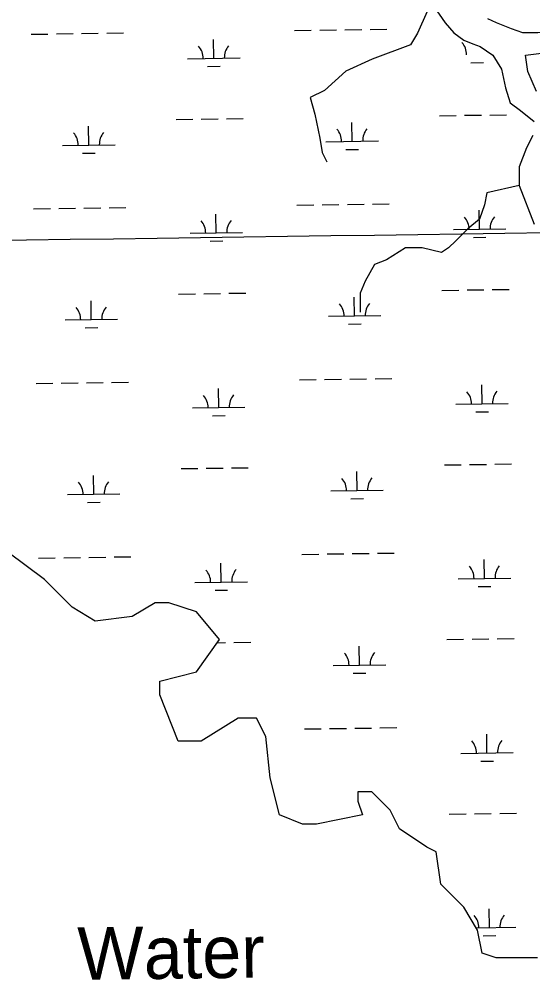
# Model space of a CAD drawing. Extents: x 3775218 to 3813389, y 343470 to 369318.
# Drawn here: x 3788802 to 3789781, y 353674 to 355504 of the extents above; entities that cross this region are included whole.
import ezdxf

# ---------------------------------------------------------------- set-up
doc = ezdxf.new("R2010")
doc.units = 0
for name, color, linetype in [('V-GRID-MAJR', 7, 'Continuous'), ('V-RIVR-IDEN', 7, 'Continuous'), ('V-TOPO-SHOR', 7, 'Continuous'), ('V-WETL-SWMP', 7, 'Continuous')]:
    doc.layers.add(name, color=color, linetype=linetype)

msp = doc.modelspace()

# ---------------------------------------------------------------- linework, layer by layer
at = {"layer": 'V-GRID-MAJR'}
msp.add_spline([(3779369.4, 354952.8), (3784672.7, 355025.7), (3789975.9, 355099.3), (3795279.1, 355173.8), (3800582.3, 355249), (3805885.5, 355325), (3811188.7, 355401.7)], degree=3, dxfattribs=at)
at = {"layer": 'V-TOPO-SHOR'}
for points in [[(3789589.8, 355547), (3789579.1, 355518.1), (3789560.9, 355477.2), (3789547.3, 355454.4), (3789474.5, 355427.2), (3789424.5, 355404.4), (3789383.6, 355368), (3789356.3, 355354.4), (3789365.4, 355322.5), (3789374.5, 355277.1), (3789379, 355249.8), (3789388.1, 355231.6)], [(3789592.2, 355527.9), (3789613.7, 355496.9), (3789630.3, 355477.8), (3789649.4, 355463.5), (3789666.1, 355456.3), (3789680.4, 355451.5), (3789704.3, 355434.8), (3789721, 355408.6), (3789728.2, 355372.8), (3789737.7, 355344.2), (3789756.8, 355329.9), (3789783, 355308.4)], [(3789921.4, 355523.1), (3789883.2, 355499.2), (3789847.4, 355482.5), (3789790.2, 355477.8), (3789761.6, 355477.8), (3789740.1, 355484.9), (3789711.5, 355496.9), (3789694.8, 355504)], [(3789787.8, 355365.7), (3789771.1, 355403.8), (3789766.3, 355434.8), (3789802.1, 355439.6)], [(3789780.6, 355282.2), (3789768.7, 355258.3), (3789754.4, 355222.5), (3789754.4, 355186.7), (3789783, 355112.8)], [(3789754.4, 355186.7), (3789692.8, 355172.5), (3789688.3, 355149.7), (3789679.2, 355122.4), (3789656.5, 355104.2), (3789633.7, 355081.5), (3789620.1, 355067.9), (3789606.4, 355058.8), (3789570, 355067.9), (3789538.2, 355067.9), (3789501.8, 355045.1), (3789479.1, 355036), (3789460.9, 355004.2), (3789451.8, 354981.4), (3789451.8, 354954.2), (3789451.8, 354945.1)], [(3789069.6, 354242.5), (3789139.8, 354260.1), (3789183.7, 354321.6), (3789139.8, 354374.3), (3789087.1, 354391.9), (3789060.8, 354391.9), (3789016.9, 354365.5), (3788946.6, 354356.7), (3788902.7, 354383.1), (3788850, 354435.8), (3788779.8, 354488.5)], [(3789789.6, 353715.3), (3789710.6, 353715.3), (3789684.2, 353724.1), (3789675.4, 353768), (3789649.1, 353811.9), (3789605.2, 353855.9), (3789596.4, 353917.4), (3789578.8, 353926.2), (3789526.2, 353961.3), (3789508.6, 353996.5), (3789473.5, 354031.6), (3789447.1, 354031.6), (3789447.1, 354014), (3789455.9, 353987.7), (3789368.1, 353970.1), (3789341.8, 353970.1), (3789297.9, 353987.7), (3789280.3, 354058), (3789271.5, 354137.1), (3789254, 354172.2), (3789218.8, 354172.2), (3789148.6, 354128.3), (3789104.7, 354128.3), (3789069.6, 354216.1), (3789069.6, 354242.5)]]:
    msp.add_lwpolyline(points, dxfattribs=at)
at = {"layer": 'V-WETL-SWMP'}
for p, q in [((3788824.6, 355474.9), (3788856.6, 355475.3)), ((3788872.6, 355475.6), (3788904.6, 355476)), ((3788920.5, 355476.2), (3788952.5, 355476.7)), ((3788968.5, 355476.9), (3789000.5, 355477.4)), ((3789326.4, 355482), (3789358.4, 355482.4)), ((3789374.4, 355482.6), (3789406.4, 355483.1)), ((3789422.4, 355483.3), (3789454.4, 355483.8)), ((3789470.4, 355484), (3789502.4, 355484.5)), ((3789172.6, 355429.1), (3789172, 355465.1)), ((3789122.6, 355428.3), (3789222.6, 355429.8)), ((3789662.6, 355420.5), (3789686.6, 355420.9)), ((3789160.8, 355413.5), (3789184.8, 355413.8)), ((3789100.8, 355312.6), (3789132.8, 355313)), ((3789148.8, 355313.3), (3789180.8, 355313.7)), ((3789196.8, 355314), (3789228.8, 355314.4)), ((3789602.6, 355319.7), (3789634.6, 355320.1)), ((3789650.6, 355320.4), (3789682.6, 355320.8)), ((3789698.6, 355321), (3789730.6, 355321.5)), ((3788934.4, 355263.8), (3788933.9, 355299.8)), ((3789436.3, 355270.9), (3789435.7, 355306.9)), ((3788884.4, 355263.1), (3788984.4, 355264.5)), ((3789386.3, 355270.2), (3789486.2, 355271.6)), ((3789424.5, 355255.3), (3789448.5, 355255.6)), ((3788922.6, 355248.2), (3788946.6, 355248.6)), ((3788973.2, 355144.3), (3789005.2, 355144.7)), ((3789331.1, 355149.3), (3789363.1, 355149.8)), ((3789379.1, 355150), (3789411.1, 355150.5)), ((3789427.1, 355150.7), (3789459.1, 355151.1)), ((3789475.1, 355151.4), (3789507.1, 355151.8)), ((3788829.3, 355142.2), (3788861.2, 355142.7)), ((3788877.2, 355142.9), (3788909.2, 355143.4)), ((3788925.2, 355143.6), (3788957.2, 355144.1)), ((3789177.2, 355096.4), (3789176.7, 355132.4)), ((3789679.1, 355103.5), (3789678.6, 355139.5)), ((3789127.3, 355095.7), (3789227.2, 355097.1)), ((3789629.1, 355102.8), (3789729.1, 355104.2)), ((3789165.5, 355080.8), (3789189.5, 355081.2)), ((3789667.3, 355087.9), (3789691.3, 355088.2)), ((3789105.5, 354980), (3789137.5, 354980.4)), ((3789153.5, 354980.6), (3789185.5, 354981.1)), ((3789201.5, 354981.3), (3789233.5, 354981.8)), ((3789607.3, 354987), (3789639.3, 354987.5)), ((3789655.3, 354987.7), (3789687.3, 354988.2)), ((3789703.3, 354988.4), (3789735.3, 354988.8)), ((3788939.1, 354931.2), (3788938.6, 354967.2)), ((3789440.9, 354938.3), (3789440.4, 354974.3)), ((3788889.1, 354930.5), (3788989.1, 354931.9)), ((3789390.9, 354937.5), (3789490.9, 354939)), ((3788927.3, 354915.6), (3788951.3, 354915.9)), ((3789429.2, 354922.7), (3789453.2, 354923)), ((3789335.8, 354816.7), (3789367.8, 354817.1)), ((3789383.8, 354817.4), (3789415.8, 354817.8)), ((3789431.8, 354818), (3789463.8, 354818.5)), ((3789479.8, 354818.7), (3789511.8, 354819.2)), ((3788833.9, 354809.6), (3788865.9, 354810.1)), ((3788881.9, 354810.3), (3788913.9, 354810.7)), ((3788929.9, 354811), (3788961.9, 354811.4)), ((3788977.9, 354811.6), (3789009.9, 354812.1)), ((3789181.9, 354763.8), (3789181.4, 354799.8)), ((3789683.8, 354770.9), (3789683.3, 354806.8)), ((3789131.9, 354763.1), (3789231.9, 354764.5)), ((3789633.8, 354770.1), (3789733.8, 354771.6)), ((3789170.2, 354748.2), (3789194.2, 354748.5)), ((3789672, 354755.3), (3789696, 354755.6)), ((3789612, 354654.4), (3789644, 354654.8)), ((3789660, 354655.1), (3789692, 354655.5)), ((3789708, 354655.7), (3789740, 354656.2)), ((3788943.8, 354598.5), (3788943.3, 354634.5)), ((3789110.2, 354647.3), (3789142.2, 354647.8)), ((3789158.2, 354648), (3789190.2, 354648.4)), ((3789206.2, 354648.7), (3789238.2, 354649.1)), ((3789445.6, 354605.6), (3789445.1, 354641.6)), ((3788893.8, 354597.8), (3788993.8, 354599.2)), ((3789395.6, 354604.9), (3789495.6, 354606.3)), ((3788932, 354582.9), (3788956, 354583.3)), ((3789433.9, 354590), (3789457.9, 354590.4)), ((3789436.5, 354485.4), (3789468.5, 354485.9)), ((3789484.5, 354486.1), (3789516.5, 354486.5)), ((3788838.6, 354477), (3788870.6, 354477.4)), ((3788886.6, 354477.6), (3788918.6, 354478.1)), ((3788934.6, 354478.3), (3788966.6, 354478.8)), ((3788982.6, 354479), (3789014.6, 354479.4)), ((3789340.5, 354484), (3789372.5, 354484.5)), ((3789388.5, 354484.7), (3789420.5, 354485.2)), ((3789688.5, 354438.2), (3789688, 354474.2)), ((3789186.6, 354431.1), (3789186.1, 354467.1)), ((3789136.6, 354430.4), (3789236.6, 354431.8)), ((3789638.5, 354437.5), (3789738.5, 354438.9)), ((3789174.9, 354415.5), (3789198.9, 354415.9)), ((3789676.7, 354422.6), (3789700.7, 354422.9)), ((3789616.7, 354321.8), (3789648.7, 354322.2)), ((3789664.7, 354322.4), (3789696.7, 354322.9)), ((3789712.7, 354323.1), (3789744.7, 354323.6)), ((3789179.4, 354315.6), (3789194.9, 354315.8)), ((3789210.9, 354316), (3789242.9, 354316.5)), ((3789450.3, 354273), (3789449.8, 354309)), ((3789400.3, 354272.3), (3789500.3, 354273.7)), ((3789438.5, 354257.4), (3789462.5, 354257.7)), ((3789345.2, 354151.4), (3789377.2, 354151.9)), ((3789393.2, 354152.1), (3789425.2, 354152.5)), ((3789441.2, 354152.8), (3789473.2, 354153.2)), ((3789489.2, 354153.4), (3789521.2, 354153.9)), ((3789693.2, 354105.6), (3789692.7, 354141.6)), ((3789643.2, 354104.9), (3789743.2, 354106.3)), ((3789681.4, 354090), (3789705.4, 354090.3)), ((3789621.4, 353989.1), (3789653.4, 353989.6)), ((3789669.4, 353989.8), (3789701.4, 353990.2)), ((3789717.4, 353990.5), (3789749.4, 353990.9)), ((3789697.9, 353772.9), (3789697.4, 353808.9)), ((3789672.7, 353772.6), (3789747.9, 353773.6)), ((3789686.1, 353757.3), (3789710.1, 353757.7))]:
    msp.add_line(p, q, dxfattribs=at)
for points in [[(3789069.6, 354242.5), (3789139.8, 354260.1), (3789183.7, 354321.6), (3789139.8, 354374.3), (3789087.1, 354391.9), (3789060.8, 354391.9), (3789016.9, 354365.5), (3788946.6, 354356.7), (3788902.7, 354383.1), (3788850, 354435.8), (3788779.8, 354488.5)], [(3789789.6, 353715.3), (3789710.6, 353715.3), (3789684.2, 353724.1), (3789675.4, 353768), (3789649.1, 353811.9), (3789605.2, 353855.9), (3789596.4, 353917.4), (3789578.8, 353926.2), (3789526.2, 353961.3), (3789508.6, 353996.5), (3789473.5, 354031.6), (3789447.1, 354031.6), (3789447.1, 354014), (3789455.9, 353987.7), (3789368.1, 353970.1), (3789341.8, 353970.1), (3789297.9, 353987.7), (3789280.3, 354058), (3789271.5, 354137.1), (3789254, 354172.2), (3789218.8, 354172.2), (3789148.6, 354128.3), (3789104.7, 354128.3), (3789069.6, 354216.1), (3789069.6, 354242.5)]]:
    msp.add_lwpolyline(points, dxfattribs=at)
for centre, start, end in [((3789619.2, 355435.8), 0.0365, 41.5802), ((3789117.3, 355428.7), 0.0365, 41.5802), ((3789227.8, 355430.3), 140.0365, 181.5802), ((3789381, 355270.6), 0.0365, 41.5802), ((3789491.5, 355272.2), 140.0365, 181.5802), ((3788879.1, 355263.5), 0.0365, 41.5802), ((3788989.6, 355265.1), 140.0365, 181.5802), ((3789623.9, 355103.2), 0.0365, 41.5802), ((3789734.3, 355104.7), 140.0365, 181.5802), ((3789122, 355096.1), 0.0365, 41.5802), ((3789232.5, 355097.7), 140.0365, 181.5802), ((3789496.2, 354939.5), 140.0365, 181.5802), ((3788883.8, 354930.9), 0.0365, 41.5802), ((3788994.3, 354932.4), 140.0365, 181.5802), ((3789385.7, 354938), 0.0365, 41.5802), ((3789126.7, 354763.5), 0.0365, 41.5802), ((3789237.2, 354765), 140.0365, 181.5802), ((3789628.6, 354770.5), 0.0365, 41.5802), ((3789739, 354772.1), 140.0365, 181.5802), ((3788888.5, 354598.2), 0.0365, 41.5802), ((3788999, 354599.8), 140.0365, 181.5802), ((3789390.4, 354605.3), 0.0365, 41.5802), ((3789500.9, 354606.9), 140.0365, 181.5802), ((3789131.4, 354430.8), 0.0365, 41.5802), ((3789241.9, 354432.4), 140.0365, 181.5802), ((3789633.3, 354437.9), 0.0365, 41.5802), ((3789743.7, 354439.5), 140.0365, 181.5802), ((3789395.1, 354272.7), 0.0365, 41.5802), ((3789505.6, 354274.2), 140.0365, 181.5802), ((3789637.9, 354105.3), 0.0365, 41.5802), ((3789748.4, 354106.8), 140.0365, 181.5802), ((3789642.6, 353772.6), 0.0365, 41.5802), ((3789753.1, 353774.2), 140.0365, 181.5802)]:
    msp.add_arc(centre, 35.2, start, end, dxfattribs=at)

# ---------------------------------------------------------------- texts
at = {"layer": 'V-RIVR-IDEN'}
msp.add_text('Water', height=100, rotation=0.7588, dxfattribs=at).set_placement((3788913.4, 353673.2))

doc.saveas('drawing.dxf')
